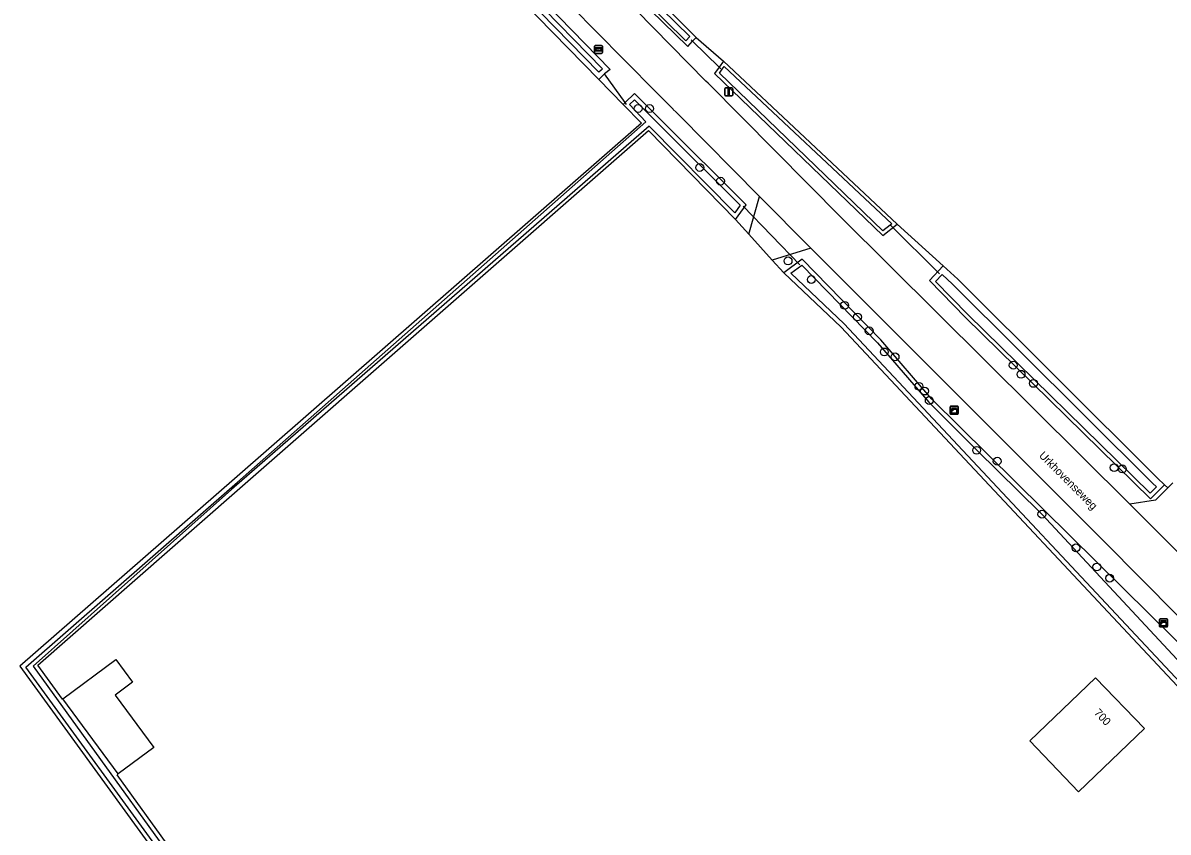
# Model space of a CAD drawing. Extents: x 164494 to 166241, y 382475 to 384494.
# Drawn here: x 165473.6 to 165616.6, y 382577 to 382678.1 of the extents above; entities that cross this region are included whole.
import ezdxf

# ---------------------------------------------------------------- set-up
doc = ezdxf.new("R2010")
doc.units = 0
for name, color, linetype in [('IMGEO_Boom', 7, 'Continuous'), ('IMGEO_Bouwland', 7, 'Continuous'), ('IMGEO_Duiker', 7, 'Continuous'), ('IMGEO_Erf', 7, 'Continuous'), ('IMGEO_Grasland_agrarisch', 7, 'Continuous'), ('IMGEO_Groenvoorziening', 7, 'Continuous'), ('IMGEO_Kast', 7, 'Continuous'), ('IMGEO_Openbare_ruimte_label', 7, 'Continuous'), ('IMGEO_Pand', 7, 'Continuous'), ('IMGEO_Pand_nummerreeks', 7, 'Continuous'), ('IMGEO_Rijbaan_lokaal_gesloten', 7, 'Continuous'), ('IMGEO_Verkeersbordpaal', 7, 'Continuous'), ('IMGEO_Voetpad_open', 7, 'Continuous'), ('IMGEO_Waterloop', 7, 'Continuous'), ('IMGEO_Wegwijzer', 7, 'Continuous')]:
    doc.layers.add(name, color=color, linetype=linetype)

msp = doc.modelspace()

# ---------------------------------------------------------------- linework, layer by layer
at = {"layer": 'IMGEO_Boom'}
for centre in [(165550.43, 382667.4), (165551.85, 382667.4), (165558.13, 382660.03), (165560.72, 382658.33), (165569.16, 382648.37), (165572.06, 382646.04), (165576.22, 382642.82), (165577.83, 382641.36), (165579.29, 382639.63), (165581.18, 382637), (165582.53, 382636.38), (165597.29, 382635.34), (165598.27, 382634.21), (165585.51, 382632.71), (165586.21, 382632.11), (165599.82, 382633.07), (165586.8, 382630.93), (165592.73, 382624.71), (165595.29, 382623.35), (165609.9, 382622.55), (165610.92, 382622.39), (165600.87, 382616.73), (165605.13, 382612.53), (165607.73, 382610.14), (165609.34, 382608.74)]:
    msp.add_circle(centre, 0.489, dxfattribs=at)
at = {"layer": 'IMGEO_Bouwland'}
for points in [[(165545.51, 382671.03), (165535.96, 382680.81), (165525.91, 382691.48), (165509, 382708.97), (165500, 382718.6), (165485.31, 382734.31), (165475.61, 382745.32)], [(165548.56, 382667.91), (165545.51, 382671.03)], [(165548.56, 382667.91), (165550.83, 382665.58), (165500, 382621.16), (165473.19, 382597.73), (165491.59, 382572.41), (165491.84, 382572.06)]]:
    msp.add_lwpolyline(points, dxfattribs=at)
at = {"layer": 'IMGEO_Duiker'}
for points in [[(165557.06, 382675.98), (165557.24, 382675.8), (165560.57, 382672.56), (165560.78, 382672.35)], [(165548.98, 382667.89), (165548.8, 382668.14), (165546.24, 382671.72)], [(165563.54, 382655.21), (165570.62, 382647.86)], [(165581.86, 382652.92), (165588.06, 382646.76)]]:
    msp.add_lwpolyline(points, dxfattribs=at)
at = {"layer": 'IMGEO_Erf'}
for points in [[(165478.55, 382593.65), (165478.51, 382593.62), (165475.44, 382597.88), (165500, 382619.38), (165551.73, 382664.66), (165562.6, 382653.53)], [(165568.63, 382646.88), (165575.78, 382640.1), (165625.79, 382586.73), (165636.94, 382574.99), (165522.62, 382530.99), (165507.33, 382553.7), (165500, 382563.85), (165485.32, 382584.19), (165485.48, 382584.31)]]:
    msp.add_lwpolyline(points, dxfattribs=at)
at = {"layer": 'IMGEO_Grasland_agrarisch'}
for points in [[(165557.68, 382676.28), (165546.89, 382687.08), (165545.33, 382688.67), (165533.02, 382701.74), (165569.4, 382731.21), (165591.95, 382750), (165602.38, 382758.68), (165616.33, 382769.76), (165629.58, 382750), (165637.97, 382737.48), (165666.88, 382693.56), (165691.22, 382656.07)], [(165557.68, 382676.28), (165561.11, 382673.32)], [(165561.11, 382673.32), (165582.8, 382652.97)], [(165582.8, 382652.97), (165588.54, 382647.76)], [(165616.2, 382620.42), (165615.33, 382621.23), (165590.35, 382646.1), (165588.54, 382647.76)], [(165616.2, 382620.42), (165616.62, 382620.02)]]:
    msp.add_lwpolyline(points, dxfattribs=at)
at = {"layer": 'IMGEO_Groenvoorziening'}
for points in [[(165475.61, 382745.32), (165476.8, 382746.34), (165486.97, 382736.07), (165500, 382721.69), (165510.36, 382710.25), (165526.14, 382693.78), (165537.4, 382682.09), (165546.95, 382672.27), (165546.24, 382671.72), (165545.51, 382671.03)], [(165516.13, 382720.35), (165515.18, 382719.58), (165514.39, 382718.95), (165533.15, 382698.96), (165544.17, 382687.49), (165545.78, 382685.78), (165556.62, 382675.15), (165557.24, 382675.8), (165557.68, 382676.28)], [(165561.11, 382673.32), (165560.57, 382672.56), (165559.98, 382671.76), (165580.98, 382651.53), (165582.8, 382652.97)], [(165562.6, 382653.53), (165563.92, 382655.38), (165553.27, 382665.99), (165549.96, 382669.28), (165548.8, 382668.14), (165548.56, 382667.91)], [(165564.24, 382651.72), (165562.6, 382653.53)], [(165568.63, 382646.88), (165567.19, 382648.47)], [(165677.62, 382538.16), (165650.8, 382566.57), (165632.21, 382585.73), (165620.95, 382597.69), (165601.06, 382617.32), (165587.14, 382631.09), (165580.76, 382638.51), (165570.92, 382648.57), (165568.63, 382646.88)], [(165588.54, 382647.76), (165586.85, 382645.93), (165591.31, 382641.32), (165614.46, 382618.67), (165616.2, 382620.42)]]:
    msp.add_lwpolyline(points, dxfattribs=at)
at = {"layer": 'IMGEO_Kast'}
for p, q in [((165589.42, 382629.29), (165589.42, 382630.14)), ((165589.42, 382630.14), (165589.42, 382629.29)), ((165589.5, 382630.22), (165590.34, 382630.22)), ((165590.34, 382630.22), (165589.5, 382630.22)), ((165590.42, 382630.15), (165590.42, 382629.3)), ((165590.42, 382629.3), (165590.42, 382630.15)), ((165590.35, 382629.22), (165589.51, 382629.22)), ((165589.51, 382629.22), (165590.35, 382629.22)), ((165615.57, 382602.72), (165615.57, 382603.56)), ((165615.57, 382603.56), (165615.57, 382602.72)), ((165615.64, 382603.65), (165616.48, 382603.65)), ((165616.48, 382603.65), (165615.64, 382603.65)), ((165616.56, 382603.57), (165616.56, 382602.73)), ((165616.56, 382602.73), (165616.56, 382603.57)), ((165616.49, 382602.65), (165615.65, 382602.65)), ((165615.65, 382602.65), (165616.49, 382602.65))]:
    msp.add_line(p, q, dxfattribs=at)
for points in [[(165589.62, 382630.01), (165590.22, 382630.01), (165590.22, 382629.92), (165589.62, 382629.92), (165589.62, 382630.01)], [(165589.62, 382629.84), (165590.22, 382629.84), (165590.22, 382629.35), (165589.62, 382629.35), (165589.62, 382629.84)], [(165615.76, 382603.44), (165616.36, 382603.44), (165616.36, 382603.35), (165615.76, 382603.35), (165615.76, 382603.44)], [(165615.76, 382603.26), (165616.36, 382603.26), (165616.36, 382602.77), (165615.76, 382602.77), (165615.76, 382603.26)]]:
    msp.add_lwpolyline(points, dxfattribs=at)
for centre in [(165589.7, 382629.68), (165615.84, 382603.11)]:
    msp.add_circle(centre, 0.0377, dxfattribs=at)
for centre, start, end in [((165589.5, 382630.14), 92.4484, 184.2845), ((165589.5, 382630.14), 92.4484, 184.2845), ((165589.5, 382629.3), 182.4484, 274.2845), ((165589.5, 382629.3), 182.4484, 274.2845), ((165590.35, 382630.14), 2.4484, 94.2845), ((165590.35, 382630.14), 2.4484, 94.2845), ((165590.35, 382629.3), 272.4484, 4.2845), ((165590.35, 382629.3), 272.4484, 4.2845), ((165615.64, 382603.57), 92.4484, 184.2845), ((165615.64, 382603.57), 92.4484, 184.2845), ((165616.49, 382603.57), 2.4484, 94.2845), ((165616.49, 382603.57), 2.4484, 94.2845), ((165615.64, 382602.72), 182.4484, 274.2845), ((165615.64, 382602.72), 182.4484, 274.2845), ((165616.49, 382602.72), 272.4484, 4.2845), ((165616.49, 382602.72), 272.4484, 4.2845)]:
    msp.add_arc(centre, 0.0779, start, end, dxfattribs=at)
at = {"layer": 'IMGEO_Pand'}
for points in [[(165478.55, 382593.65), (165485.17, 382598.57), (165487.27, 382595.74), (165485.09, 382594.13), (165489.93, 382587.61), (165485.48, 382584.31)], [(165607.59, 382596.3), (165613.68, 382589.95), (165605.44, 382582.05), (165599.35, 382588.41), (165607.59, 382596.3)], [(165485.48, 382584.31), (165478.55, 382593.65)]]:
    msp.add_lwpolyline(points, dxfattribs=at)
at = {"layer": 'IMGEO_Rijbaan_lokaal_gesloten'}
for points in [[(165611.85, 382617.98), (165575.84, 382653.73), (165559.16, 382670.56), (165558.9, 382670.83), (165541.43, 382688.62)], [(165554.8, 382667.3), (165555.17, 382666.93), (165555.54, 382666.56), (165565.6, 382656.4)], [(165565.6, 382656.4), (165572, 382649.98)], [(165572, 382649.98), (165608.7, 382613.27), (165658.65, 382562.86), (165681.33, 382539.89)], [(165619.42, 382610.4), (165611.85, 382617.98)]]:
    msp.add_lwpolyline(points, dxfattribs=at)
msp.add_arc((166862.27, 383970.43), 1845.97, 224.14065, 224.9045, dxfattribs=at)
at = {"layer": 'IMGEO_Verkeersbordpaal'}
for p, q in [((165561.25, 382669.08), (165561.25, 382669.88)), ((165561.25, 382669.88), (165561.25, 382669.08)), ((165561.35, 382669.98), (165562.14, 382669.98)), ((165562.14, 382669.98), (165561.35, 382669.98)), ((165562.24, 382669.88), (165562.24, 382669.08)), ((165562.24, 382669.08), (165562.24, 382669.88)), ((165562.14, 382668.98), (165561.35, 382668.98)), ((165561.35, 382668.98), (165562.14, 382668.98))]:
    msp.add_line(p, q, dxfattribs=at)
msp.add_lwpolyline([(165561.67, 382669.86), (165561.82, 382669.86), (165561.82, 382669.11), (165561.67, 382669.11), (165561.67, 382669.86)], dxfattribs=at)
for centre, start, end in [((165561.35, 382669.88), 90, 180), ((165561.35, 382669.88), 90, 180), ((165562.14, 382669.88), 0, 90), ((165562.14, 382669.88), 360, 90), ((165561.35, 382669.08), 180, 270), ((165561.35, 382669.08), 180, 270), ((165562.14, 382669.08), 270, 0), ((165562.14, 382669.08), 270, 0)]:
    msp.add_arc(centre, 0.1, start, end, dxfattribs=at)
at = {"layer": 'IMGEO_Voetpad_open'}
for points in [[(165564.24, 382651.72), (165565.6, 382656.4)], [(165567.19, 382648.47), (165564.24, 382651.72)], [(165572, 382649.98), (165567.19, 382648.47)], [(165616.62, 382620.02), (165615.07, 382618.47), (165611.85, 382617.98)], [(165617.25, 382620.65), (165616.62, 382620.02)]]:
    msp.add_lwpolyline(points, dxfattribs=at)
at = {"layer": 'IMGEO_Waterloop'}
for points in [[(165617.58, 382770.8), (165616.48, 382770.72), (165601.96, 382759.2), (165591.53, 382750.51), (165568.98, 382731.73), (165532.05, 382701.69), (165544.85, 382688.22), (165546.42, 382686.62), (165556.9, 382676.38), (165556.39, 382675.86), (165546.03, 382686.08), (165544.26, 382687.85), (165533.38, 382699.18), (165515.36, 382718.88), (165515.6, 382719.07), (165516.06, 382719.44), (165531.51, 382702.16), (165566.3, 382730.96), (165588.85, 382749.49), (165602.07, 382760.34), (165615.11, 382770.94), (165617.83, 382772.76)], [(165485.78, 382734.74), (165476.52, 382745.25), (165476.77, 382745.46), (165486.5, 382735.63), (165499.52, 382721.26), (165509.89, 382709.81), (165525.68, 382693.34), (165536.93, 382681.65), (165545.99, 382672.34), (165545.82, 382672.2), (165545.53, 382671.93), (165536.42, 382681.26), (165526.38, 382691.92), (165509.46, 382709.42), (165500.47, 382719.04), (165485.78, 382734.74)], [(165561.18, 382672.64), (165582.11, 382653), (165581.93, 382652.85), (165581.01, 382652.13), (165560.58, 382671.81), (165560.93, 382672.3), (165561.18, 382672.64)], [(165492.04, 382572.73), (165473.94, 382597.64), (165500.37, 382620.74), (165551.39, 382665.75), (165549.35, 382667.9), (165549.96, 382668.49), (165552.87, 382665.59), (165563.19, 382655.32), (165562.53, 382654.39), (165551.8, 382665.21), (165499.63, 382619.8), (165474.85, 382597.75), (165499.55, 382563.53)], [(165626.19, 382587.12), (165576.18, 382640.5), (165569.5, 382646.83), (165570.86, 382647.84), (165580.35, 382638.13), (165586.73, 382630.71), (165592.73, 382624.71), (165600.67, 382616.93), (165600.87, 382616.73), (165619.45, 382596.8)], [(165588.4, 382646.69), (165589.7, 382645.48), (165614.69, 382620.62), (165615.21, 382620.13), (165614.41, 382619.34), (165591.6, 382641.66), (165587.59, 382645.81), (165588.4, 382646.69)]]:
    msp.add_lwpolyline(points, dxfattribs=at)
at = {"layer": 'IMGEO_Wegwijzer'}
for p, q in [((165544.98, 382674.39), (165544.98, 382675.18)), ((165544.98, 382675.18), (165544.98, 382674.39)), ((165545.08, 382675.28), (165545.87, 382675.28)), ((165545.87, 382675.28), (165545.08, 382675.28)), ((165545.97, 382675.18), (165545.97, 382674.39)), ((165545.97, 382674.39), (165545.97, 382675.18)), ((165545.87, 382674.29), (165545.08, 382674.29)), ((165545.08, 382674.29), (165545.87, 382674.29))]:
    msp.add_line(p, q, dxfattribs=at)
for points in [[(165545.09, 382675.02), (165545.87, 382675.02), (165545.87, 382674.55), (165545.09, 382674.55), (165545.09, 382675.02)], [(165545.15, 382674.87), (165545.15, 382674.79), (165545.15, 382674.7), (165545.56, 382674.7), (165545.56, 382674.62), (165545.81, 382674.79), (165545.56, 382674.95), (165545.56, 382674.87), (165545.15, 382674.87)]]:
    msp.add_lwpolyline(points, dxfattribs=at)
for centre, start, end in [((165545.08, 382675.18), 90, 180), ((165545.08, 382675.18), 90, 180), ((165545.87, 382675.18), 0, 90), ((165545.87, 382675.18), 360, 90), ((165545.08, 382674.39), 180, 270), ((165545.08, 382674.39), 180, 270), ((165545.87, 382674.39), 270, 0), ((165545.87, 382674.39), 270, 0)]:
    msp.add_arc(centre, 0.1, start, end, dxfattribs=at)

# ---------------------------------------------------------------- texts
at = {"layer": 'IMGEO_Openbare_ruimte_label'}
msp.add_text('Urkhovenseweg', height=1, rotation=314.9595, dxfattribs=at).set_placement((165600.44, 382623.98))
at = {"layer": 'IMGEO_Pand_nummerreeks'}
msp.add_text('700', height=1, rotation=313.7914, dxfattribs=at).set_placement((165607.32, 382591.85))

doc.saveas('drawing.dxf')
